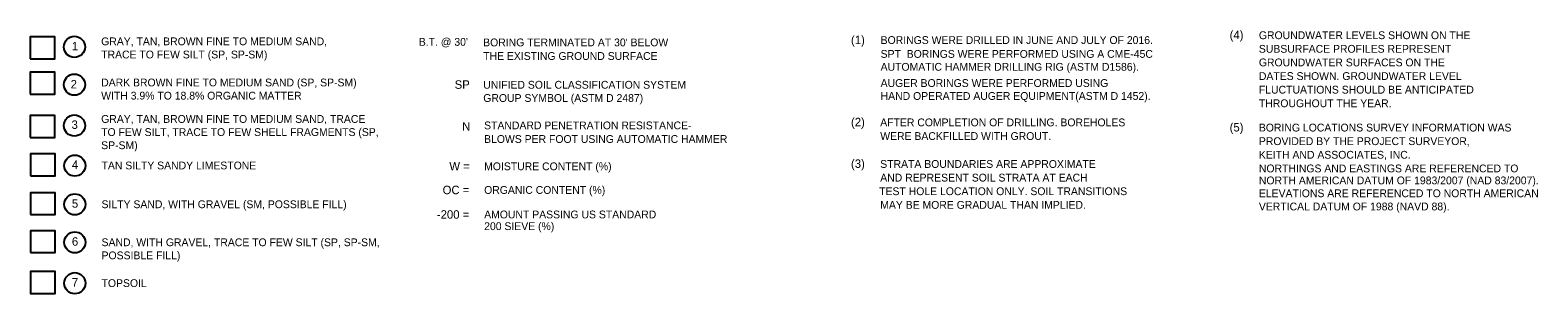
# Model space of a CAD drawing. Extents: x 0 to 331, y -72 to 117.
# Drawn here: x 27.39 to 54.47, y -28.18 to -23.45 of the extents above; entities that cross this region are included whole.
import ezdxf

# ---------------------------------------------------------------- set-up
doc = ezdxf.new("R2010")
doc.units = 0
doc.layers.add('1-BORE', color=7, linetype='Continuous')
doc.layers.add('1-TEXT', color=7, linetype='Continuous')

msp = doc.modelspace()

# ---------------------------------------------------------------- linework, layer by layer
at = {"layer": '1-BORE'}
msp.add_lwpolyline([(27.843, -28.175), (27.843, -27.782), (27.401, -27.782), (27.401, -28.175), (27.843, -28.175), (27.843, -28.175)], dxfattribs=at)
at = {"layer": '1-TEXT'}
for points in [[(27.395, -23.963), (27.837, -23.963), (27.837, -23.57), (27.395, -23.57)], [(27.395, -24.598), (27.837, -24.598), (27.837, -24.205), (27.395, -24.205)], [(27.395, -25.374), (27.837, -25.374), (27.837, -24.981), (27.395, -24.981)], [(27.401, -26.065), (27.843, -26.065), (27.843, -25.672), (27.401, -25.672)], [(27.401, -26.761), (27.843, -26.761), (27.843, -26.368), (27.401, -26.368)], [(27.401, -27.442), (27.843, -27.442), (27.843, -27.049), (27.401, -27.049)], [(27.401, -28.175), (27.843, -28.175), (27.843, -27.782), (27.401, -27.782)]]:
    msp.add_lwpolyline(points, close=True, dxfattribs=at)
for centre in [(28.19, -23.751), (28.19, -24.429), (28.19, -25.163), (28.197, -25.881), (28.197, -26.577), (28.197, -27.259), (28.197, -27.992)]:
    msp.add_circle(centre, 0.19, dxfattribs=at)

# ---------------------------------------------------------------- texts
for s, height, p in [('(1)', 0.1521, (42.134, -23.702)), ('(4)', 0.1521, (48.933, -23.612)), ('GROUNDWATER LEVELS SHOWN ON THE ', 0.14, (49.458, -23.612)), ('1', 0.152, (28.144, -23.814)), ('TRACE TO FEW SILT (SP, SP-SM)', 0.14, (28.67, -23.958)), ('GRAY, TAN, BROWN FINE TO MEDIUM SAND, ', 0.14, (28.67, -23.722)), ("B.T. @ 30'", 0.14, (34.374, -23.731)), ("BORING TERMINATED AT 30' BELOW", 0.14, (35.529, -23.741)), ('SPT  BORINGS WERE PERFORMED USING A CME-45C', 0.14, (42.666, -23.947)), ('BORINGS WERE DRILLED IN JUNE AND JULY OF 2016.', 0.14, (42.666, -23.699)), ('SUBSURFACE PROFILES REPRESENT', 0.14, (49.458, -23.856)), ('THE EXISTING GROUND SURFACE', 0.14, (35.529, -23.985)), ('AUTOMATIC HAMMER DRILLING RIG (ASTM D1586).', 0.14, (42.666, -24.179)), ('GROUNDWATER SURFACES ON THE', 0.14, (49.458, -24.1)), ('2', 0.152, (28.122, -24.497)), ('DARK BROWN FINE TO MEDIUM SAND (SP, SP-SM) ', 0.14, (28.67, -24.46)), ('SP', 0.1521, (35.017, -24.503)), ('UNIFIED SOIL CLASSIFICATION SYSTEM', 0.14, (35.531, -24.501)), ('AUGER BORINGS WERE PERFORMED USING', 0.14, (42.666, -24.47)), ('DATES SHOWN. GROUNDWATER LEVEL', 0.14, (49.458, -24.345)), ('WITH 3.9% TO 18.8% ORGANIC MATTER', 0.14, (28.67, -24.696)), ('GROUP SYMBOL (ASTM D 2487)', 0.14, (35.531, -24.738)), ('HAND OPERATED AUGER EQUIPMENT(ASTM D 1452).', 0.14, (42.666, -24.702)), ('FLUCTUATIONS SHOULD BE ANTICIPATED ', 0.14, (49.458, -24.589)), ('THROUGHOUT THE YEAR.', 0.14, (49.458, -24.833)), ('3', 0.152, (28.138, -25.223)), ('GRAY, TAN, BROWN FINE TO MEDIUM SAND, TRACE ', 0.14, (28.67, -25.114)), ('N', 0.152, (35.152, -25.255)), ('STANDARD PENETRATION RESISTANCE-', 0.14, (35.546, -25.23)), ('(2)', 0.1521, (42.134, -25.176)), ('AFTER COMPLETION OF DRILLING. BOREHOLES', 0.14, (42.659, -25.176)), ('(5)', 0.1521, (48.933, -25.269)), ('BORING LOCATIONS SURVEY INFORMATION WAS', 0.14, (49.458, -25.269)), ('TO FEW SILT, TRACE TO FEW SHELL FRAGMENTS (SP, ', 0.14, (28.67, -25.35)), ('SP-SM)', 0.14, (28.67, -25.586)), ('BLOWS PER FOOT USING AUTOMATIC HAMMER', 0.14, (35.546, -25.474)), ('WERE BACKFILLED WITH GROUT.', 0.14, (42.659, -25.421)), ('PROVIDED BY THE PROJECT SURVEYOR,  ', 0.14, (49.458, -25.513)), ('KEITH AND ASSOCIATES, INC.', 0.14, (49.458, -25.757)), ('4', 0.152, (28.144, -25.941)), ('TAN SILTY SANDY LIMESTONE', 0.14, (28.677, -25.949)), ('W =', 0.1521, (34.922, -25.969)), ('MOISTURE CONTENT (%)', 0.14, (35.547, -25.964)), ('(3)', 0.1521, (42.134, -25.922)), ('STRATA BOUNDARIES ARE APPROXIMATE', 0.14, (42.659, -25.922)), ('NORTHINGS AND EASTINGS ARE REFERENCED TO ', 0.14, (49.458, -26.002)), ('OC =', 0.1521, (34.801, -26.394)), ('ORGANIC CONTENT (%)', 0.14, (35.547, -26.388)), ('AND REPRESENT SOIL STRATA AT EACH', 0.14, (42.659, -26.167)), ('NORTH AMERICAN DATUM OF 1983/2007 (NAD 83/2007).', 0.14, (49.458, -26.217)), ('5', 0.152, (28.144, -26.637)), ('SILTY SAND, WITH GRAVEL (SM, POSSIBLE FILL)', 0.14, (28.677, -26.645)), ('TEST HOLE LOCATION ONLY. SOIL TRANSITIONS', 0.14, (42.64, -26.411)), ('MAY BE MORE GRADUAL THAN IMPLIED.', 0.14, (42.659, -26.656)), ('ELEVATIONS ARE REFERENCED TO NORTH AMERICAN', 0.14, (49.458, -26.448)), ('-200 =', 0.1521, (34.698, -26.834)), ('AMOUNT PASSING US STANDARD', 0.14, (35.547, -26.828)), ('VERTICAL DATUM OF 1988 (NAVD 88).', 0.14, (49.458, -26.685)), ('200 SIEVE (%)', 0.14, (35.547, -27.038)), ('6', 0.152, (28.144, -27.319)), ('SAND, WITH GRAVEL, TRACE TO FEW SILT (SP, SP-SM, ', 0.14, (28.677, -27.327)), ('POSSIBLE FILL)', 0.14, (28.677, -27.562)), ('7', 0.152, (28.144, -28.052)), ('TOPSOIL', 0.14, (28.677, -28.06))]:
    msp.add_text(s, height=height, dxfattribs=at).set_placement(p)

doc.saveas('drawing.dxf')
